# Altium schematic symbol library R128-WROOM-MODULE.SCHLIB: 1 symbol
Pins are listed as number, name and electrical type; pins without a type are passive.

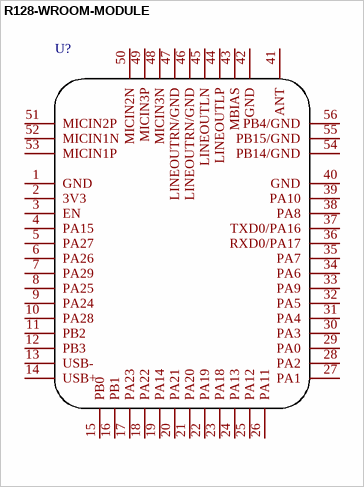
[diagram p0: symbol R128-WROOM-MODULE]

## R128-WROOM-MODULE
designator U?  (value not drawn)
Add into BOM: yes
footprint R128-WROOM-MODULE
pins: 1 GND, 2 3V3, 3 EN, 4 PA15, 5 PA27, 6 PA26, 7 PA29, 8 PA25, 9 PA24, 10 PA28, 11 PB2, 12 PB3, 13 USB-, 14 USB+, 15 PB0, 16 PB1, 17 PA23, 18 PA22, 19 PA14, 20 PA21, 21 PA20, 22 PA19, 23 PA18, 24 PA13, 25 PA12, 26 PA11, 27 PA1, 28 PA2, 29 PA0, 30 PA3, 31 PA4, 32 PA5, 33 PA9, 34 PA6, 35 PA7, 36 RXD0/PA17, 37 TXD0/PA16, 38 PA8, 39 PA10, 40 GND, 41 ANT, 42 GND, 43 MBIAS, 44 LINEOUTLP, 45 LINEOUTLN, 46 LINEOUTRN/GND, 47 LINEOUTRN/GND, 48 MICIN3N, 49 MICIN3P, 50 MICIN2N, 51 MICIN2P, 52 MICIN1N, 53 MICIN1P, 54 PB14/GND, 55 PB15/GND, 56 PB4/GND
